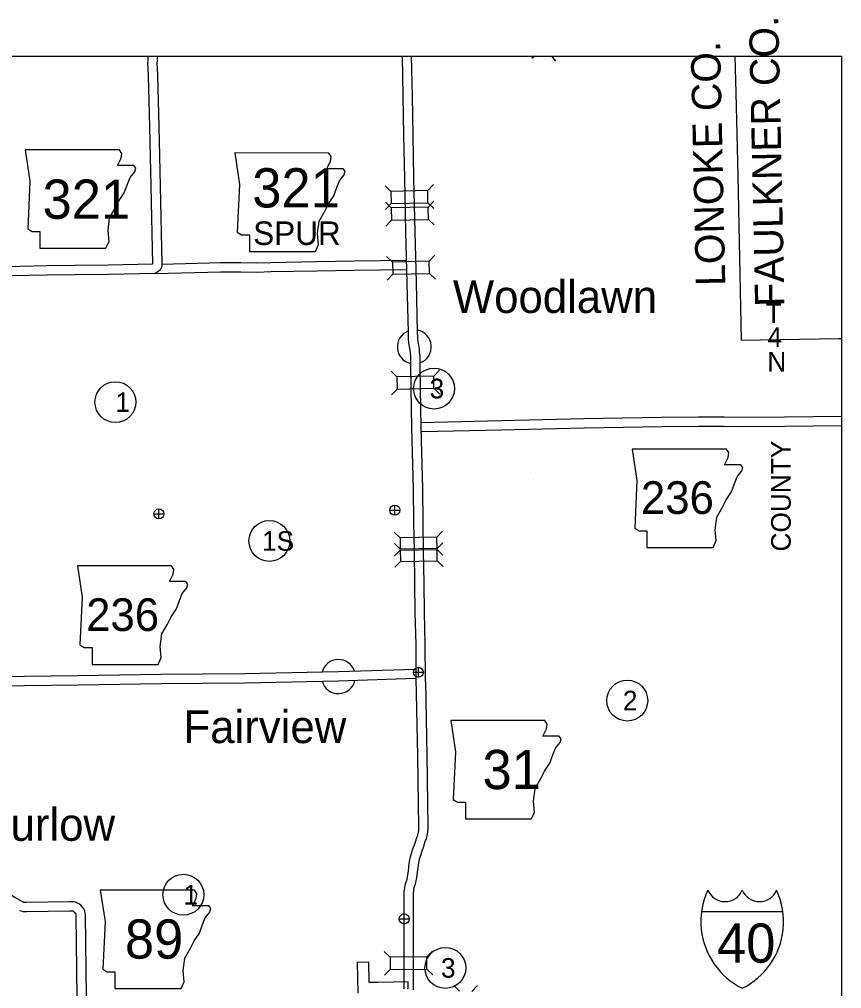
# Model space of a CAD drawing. Extents: x 1127717 to 1741049, y 2026793 to 2244711.
# Drawn here: x 1256180 to 1269452, y 2140586 to 2156238 of the extents above; entities that cross this region are included whole.
import ezdxf

# ---------------------------------------------------------------- set-up
doc = ezdxf.new("R2010")
doc.units = 0
for name, color, linetype in [('1', 7, 'Continuous'), ('10', 7, 'Continuous'), ('2', 7, 'Continuous'), ('20', 7, 'Continuous'), ('21', 7, 'Continuous'), ('23', 7, 'Continuous'), ('24', 7, 'Continuous'), ('26', 7, 'Continuous'), ('27', 7, 'Continuous'), ('30', 7, 'Continuous'), ('6', 7, 'Continuous'), ('Level 30', 7, 'Continuous')]:
    doc.layers.add(name, color=color, linetype=linetype)

msp = doc.modelspace()

# ---------------------------------------------------------------- linework, layer by layer
at = {"layer": '1'}
msp.add_lwpolyline([(1238438, 2155644), (1269452, 2155644), (1269452, 2123596), (1238438, 2123596)], close=True, dxfattribs=at)
at = {"layer": '10'}
for points in [[(1258253, 2155644), (1258252, 2155577), (1258250, 2155524), (1258252, 2155447), (1258257, 2155320), (1258274, 2154716), (1258287, 2154267), (1258300, 2153544), (1258330, 2152283)], [(1258403, 2155644), (1258402, 2155572), (1258400, 2155524), (1258402, 2155452), (1258407, 2155324), (1258424, 2154720), (1258437, 2154271), (1258450, 2153547), (1258480, 2152298), (1258481, 2152259), (1258474, 2152233), (1258463, 2152211), (1258442, 2152181), (1258420, 2152165), (1258401, 2152153), (1258374, 2152134)], [(1262356, 2155644), (1262369, 2154994), (1262382, 2154373), (1262394, 2153669), (1262414, 2152805), (1262433, 2151979), (1262453, 2151186), (1262455, 2151092), (1262463, 2151005), (1262473, 2150957), (1262482, 2150899), (1262486, 2150851), (1262495, 2150786), (1262494, 2150645), (1262500, 2150281), (1262509, 2149646), (1262526, 2149047), (1262537, 2148654), (1262541, 2148124), (1262550, 2147645), (1262559, 2147129), (1262562, 2146660)], [(1262506, 2155644), (1262519, 2154997), (1262532, 2154376), (1262544, 2153672), (1262564, 2152808), (1262583, 2151983), (1262603, 2151190), (1262605, 2151100), (1262612, 2151027), (1262621, 2150983), (1262631, 2150917), (1262635, 2150868), (1262645, 2150795), (1262644, 2150646), (1262650, 2150284), (1262659, 2149649), (1262676, 2149052), (1262687, 2148657), (1262691, 2148126), (1262700, 2147648), (1262709, 2147130), (1262712, 2146661)], [(1258480, 2152287), (1259431, 2152310), (1259754, 2152310), (1260012, 2152307), (1260240, 2152314), (1260976, 2152329), (1261586, 2152340), (1262425, 2152347)], [(1258330, 2152283), (1257618, 2152268), (1257079, 2152262), (1256625, 2152256), (1255747, 2152239), (1255057, 2152225), (1254450, 2152215), (1254187, 2152211), (1253903, 2152201), (1253598, 2152196), (1253075, 2152186)], [(1258374, 2152134), (1259433, 2152160), (1259753, 2152160), (1260013, 2152157), (1260244, 2152164), (1260979, 2152179), (1261588, 2152190), (1262428, 2152197)], [(1258374, 2152134), (1257621, 2152118), (1257081, 2152112), (1256627, 2152106), (1255750, 2152089), (1255059, 2152075), (1254452, 2152065), (1254191, 2152061), (1253907, 2152051), (1253600, 2152046), (1253078, 2152036)], [(1269452, 2149824), (1268531, 2149813), (1267859, 2149808), (1267554, 2149814), (1267143, 2149814), (1266551, 2149808), (1265291, 2149789), (1263954, 2149756), (1262665, 2149724)], [(1269452, 2149674), (1268533, 2149663), (1267859, 2149658), (1267553, 2149664), (1267144, 2149664), (1266553, 2149658), (1265294, 2149639), (1263957, 2149606), (1262674, 2149575)], [(1262562, 2146658), (1262577, 2146138), (1262581, 2145599), (1262608, 2144346)], [(1262712, 2146662), (1262727, 2146141), (1262731, 2145601), (1262732, 2145541)], [(1254588, 2145470), (1255822, 2145476), (1257131, 2145492), (1258467, 2145513), (1259821, 2145523), (1261333, 2145555), (1262576, 2145597)], [(1254592, 2145620), (1255821, 2145626), (1257129, 2145642), (1258465, 2145663), (1259819, 2145673), (1261329, 2145705), (1262572, 2145747)], [(1262734, 2145541), (1262758, 2144349), (1262771, 2143191), (1262770, 2143112), (1262758, 2143058), (1262745, 2143005), (1262726, 2142955), (1262702, 2142881), (1262668, 2142787), (1262652, 2142737), (1262632, 2142671), (1262622, 2142619), (1262610, 2142534), (1262601, 2142466), (1262594, 2142407), (1262584, 2142354), (1262574, 2142300), (1262562, 2142257), (1262549, 2142214), (1262543, 2142184), (1262539, 2142160), (1262535, 2142133), (1262534, 2142099), (1262534, 2142047), (1262537, 2141968), (1262535, 2141165), (1262538, 2140818), (1262536, 2140644), (1262535, 2140605), (1262535, 2140566)], [(1262608, 2144347), (1262621, 2143191), (1262620, 2143130), (1262612, 2143093), (1262601, 2143049), (1262585, 2143004), (1262561, 2142930), (1262526, 2142837), (1262508, 2142782), (1262486, 2142706), (1262474, 2142643), (1262461, 2142554), (1262453, 2142485), (1262446, 2142430), (1262437, 2142382), (1262428, 2142334), (1262418, 2142300), (1262403, 2142252), (1262395, 2142211), (1262390, 2142182), (1262385, 2142145), (1262384, 2142101), (1262385, 2142044), (1262387, 2141965), (1262385, 2141164), (1262388, 2140818), (1262386, 2140648), (1262385, 2140608), (1262385, 2140589), (1262381, 2140578)], [(1256242, 2141982), (1256202, 2142001), (1256109, 2142059), (1255955, 2142152), (1255752, 2142269), (1255520, 2142382), (1255074, 2142597), (1255029, 2142612), (1254988, 2142619), (1254945, 2142631), (1254924, 2142635)], [(1257115, 2140445), (1257096, 2141771), (1257095, 2141787), (1257092, 2141792), (1257083, 2141805), (1257068, 2141822), (1257061, 2141827), (1257047, 2141834), (1257042, 2141836), (1257039, 2141837), (1257024, 2141837), (1256991, 2141836), (1256298, 2141825), (1256270, 2141826), (1256246, 2141827), (1256210, 2141835), (1256184, 2141844)], [(1257265, 2140447), (1257246, 2141776), (1257244, 2141804), (1257238, 2141840), (1257218, 2141873), (1257201, 2141899), (1257171, 2141932), (1257141, 2141955), (1257107, 2141972), (1257086, 2141980), (1257055, 2141987), (1257022, 2141987), (1256986, 2141986), (1256300, 2141975), (1256277, 2141975), (1256266, 2141976), (1256251, 2141979), (1256234, 2141985)]]:
    msp.add_lwpolyline(points, dxfattribs=at)
at = {"layer": '2'}
msp.add_lwpolyline([(1267729, 2155644), (1267745, 2155053), (1267774, 2153717), (1267804, 2152380), (1267830, 2151060), (1269404, 2151085), (1269452, 2151087)], dxfattribs=at)
at = {"layer": '20'}
for p, q in [((1264504, 2155644), (1264454, 2155604)), ((1264770, 2155644), (1264836, 2155562)), ((1262177, 2153461), (1262082, 2153552)), ((1262771, 2153474), (1262862, 2153570)), ((1262183, 2153194), (1262088, 2153285)), ((1262181, 2153263), (1262090, 2153168)), ((1262775, 2153276), (1262871, 2153185)), ((1262777, 2153207), (1262868, 2153303)), ((1262188, 2152996), (1262096, 2152900)), ((1262781, 2153009), (1262877, 2152918)), ((1262203, 2152320), (1262108, 2152411)), ((1262797, 2152334), (1262888, 2152429)), ((1262208, 2152122), (1262117, 2152026)), ((1262802, 2152136), (1262897, 2152045)), ((1262275, 2150467), (1262180, 2150558)), ((1262869, 2150478), (1262960, 2150573)), ((1262278, 2150269), (1262187, 2150174)), ((1262872, 2150280), (1262967, 2150188)), ((1262324, 2147867), (1262229, 2147958)), ((1262918, 2147877), (1263010, 2147972)), ((1262922, 2147692), (1263013, 2147787)), ((1262328, 2147683), (1262233, 2147774)), ((1262328, 2147669), (1262236, 2147574)), ((1262922, 2147679), (1263017, 2147588)), ((1262331, 2147485), (1262239, 2147390)), ((1262925, 2147494), (1263020, 2147402)), ((1262164, 2141094), (1262070, 2141187)), ((1262758, 2141098), (1262850, 2141192)), ((1262165, 2140896), (1262072, 2140802)), ((1262759, 2140900), (1262853, 2140808)), ((1263285, 2140542), (1263192, 2140635)), ((1263483, 2140541), (1263577, 2140634))]:
    msp.add_line(p, q, dxfattribs=at)
for points in [[(1262181, 2153263), (1262775, 2153276), (1262771, 2153474), (1262177, 2153461)], [(1262777, 2153207), (1262183, 2153194), (1262188, 2152996), (1262781, 2153009)], [(1262797, 2152334), (1262203, 2152320), (1262208, 2152122), (1262802, 2152136)], [(1262278, 2150269), (1262872, 2150280), (1262869, 2150478), (1262275, 2150467)], [(1262328, 2147669), (1262922, 2147679), (1262918, 2147877), (1262324, 2147867)], [(1262331, 2147485), (1262925, 2147494), (1262922, 2147692), (1262328, 2147683)], [(1262758, 2141098), (1262164, 2141094), (1262165, 2140896), (1262759, 2140900)]]:
    msp.add_lwpolyline(points, close=True, dxfattribs=at)
at = {"layer": '21'}
for points in [[(1256275, 2154133), (1256351, 2153626), (1256318, 2152856), (1256385, 2152813), (1256512, 2152813), (1256512, 2152543), (1257578, 2152543), (1257629, 2152653), (1257612, 2152830), (1257637, 2153033), (1257730, 2153194), (1257789, 2153313), (1257874, 2153439), (1257925, 2153575), (1257967, 2153685), (1258043, 2153778), (1258060, 2153837), (1258026, 2153879), (1257764, 2153879), (1257823, 2153998), (1257832, 2154074), (1257797, 2154132)], [(1259655, 2154081), (1259731, 2153573), (1259697, 2152804), (1259765, 2152761), (1259892, 2152761), (1259892, 2152491), (1260958, 2152491), (1261008, 2152601), (1260991, 2152778), (1261017, 2152981), (1261110, 2153142), (1261169, 2153260), (1261254, 2153387), (1261304, 2153523), (1261347, 2153633), (1261423, 2153726), (1261440, 2153785), (1261406, 2153827), (1261144, 2153827), (1261203, 2153946), (1261211, 2154022), (1261176, 2154080)], [(1266073, 2149300), (1266149, 2148793), (1266115, 2148023), (1266183, 2147981), (1266310, 2147981), (1266310, 2147710), (1267376, 2147710), (1267426, 2147820), (1267410, 2147997), (1267435, 2148200), (1267528, 2148361), (1267587, 2148480), (1267672, 2148607), (1267723, 2148742), (1267765, 2148852), (1267841, 2148945), (1267858, 2149004), (1267824, 2149046), (1267562, 2149046), (1267621, 2149165), (1267629, 2149241), (1267594, 2149299)], [(1257116, 2147412), (1257192, 2146905), (1257158, 2146135), (1257226, 2146093), (1257353, 2146093), (1257353, 2145822), (1258419, 2145822), (1258470, 2145932), (1258453, 2146110), (1258478, 2146313), (1258571, 2146473), (1258630, 2146592), (1258715, 2146719), (1258766, 2146854), (1258808, 2146964), (1258884, 2147057), (1258901, 2147116), (1258867, 2147158), (1258605, 2147158), (1258664, 2147277), (1258673, 2147353), (1258638, 2147411)], [(1263142, 2144917), (1263218, 2144410), (1263184, 2143640), (1263252, 2143598), (1263379, 2143598), (1263379, 2143327), (1264444, 2143327), (1264495, 2143437), (1264478, 2143615), (1264504, 2143818), (1264597, 2143979), (1264656, 2144097), (1264741, 2144224), (1264791, 2144359), (1264834, 2144469), (1264910, 2144562), (1264927, 2144621), (1264893, 2144664), (1264631, 2144664), (1264690, 2144782), (1264698, 2144858), (1264663, 2144917)], [(1257486, 2142177), (1257562, 2141670), (1257529, 2140900), (1257596, 2140858), (1257723, 2140858), (1257723, 2140587), (1258789, 2140587), (1258840, 2140697), (1258823, 2140875), (1258848, 2141078), (1258941, 2141238), (1259000, 2141357), (1259085, 2141484), (1259136, 2141619), (1259178, 2141729), (1259254, 2141822), (1259271, 2141881), (1259237, 2141924), (1258975, 2141924), (1259034, 2142042), (1259043, 2142118), (1259008, 2142177)]]:
    msp.add_lwpolyline(points, close=True, dxfattribs=at)
at = {"layer": '23'}
msp.add_line((1267193, 2141833), (1268503, 2141833), dxfattribs=at)
for centre, radius, start, end in [((1268411, 2141662), 1230, 155.2204, 185.7928), ((1267571, 2142291), 300, 202.1459, 337.3414), ((1268125, 2142291), 300, 202.6586, 337.8541), ((1267285, 2141662), 1230, 354.2072, 24.7796), ((1268388, 2141673), 1209, 186.3923, 243.4571), ((1267308, 2141673), 1209, 296.5429, 353.6077)]:
    msp.add_arc(centre, radius, start, end, dxfattribs=at)
at = {"layer": '24'}
for centre, start, end in [((1265546, 2155918), 264.8657, 275.1343), ((1262555, 2150950), 112.4902, 256.9056), ((1262555, 2150950), 290.09, 79.785), ((1261329, 2145625), 19.7855, 163.6903), ((1261329, 2145625), 195.9697, 346.6075)]:
    msp.add_arc(centre, 275, start, end, dxfattribs=at)
at = {"layer": '26'}
for p, q in [((1258351, 2148252), (1258514, 2148252)), ((1258432, 2148171), (1258432, 2148333)), ((1262157, 2148313), (1262320, 2148313)), ((1262239, 2148231), (1262239, 2148394)), ((1262620, 2145612), (1262620, 2145775)), ((1262539, 2145694), (1262701, 2145694)), ((1262311, 2141711), (1262473, 2141711)), ((1262392, 2141629), (1262392, 2141792))]:
    msp.add_line(p, q, dxfattribs=at)
for centre in [(1258432, 2148252), (1262239, 2148313), (1262620, 2145694), (1262392, 2141711)]:
    msp.add_circle(centre, 81.2, dxfattribs=at)
at = {"layer": '27'}
for centre in [(1262873, 2150276), (1257730, 2150057), (1260215, 2147815), (1265992, 2145237), (1258827, 2142102), (1263056, 2140920)]:
    msp.add_circle(centre, 330, dxfattribs=at)
at = {"layer": '30'}
msp.add_line((1264429, 2148925), (1264429, 2148925), dxfattribs=at)
at = {"layer": '6'}
msp.add_lwpolyline([(1262452, 2140584), (1262454, 2140601), (1262455, 2140615), (1262456, 2140644), (1262457, 2140669), (1262458, 2140698), (1261970, 2140686), (1261824, 2140683), (1261818, 2141014), (1261631, 2141010), (1261642, 2140513)], dxfattribs=at)

# ---------------------------------------------------------------- texts
at = {"layer": '21'}
for s, height, p in [('321', 633.6, (1259939, 2153201)), ('321', 633.6, (1256554, 2153018)), ('SPUR', 380.2, (1259954, 2152595)), ('236', 528, (1266212, 2148251)), ('236', 528, (1257257, 2146361)), ('31', 633.6, (1263655, 2143808)), ('89', 633.6, (1257883, 2141070))]:
    msp.add_text(s, height=height, dxfattribs=at).set_placement(p)
at = {"layer": '23'}
msp.add_text('40', height=633.6, dxfattribs=at).set_placement((1267440, 2141004))
at = {"layer": '24'}
for s, p in [('Woodlawn', (1263177, 2151497)), ('Fairview', (1258829, 2144551)), ('Furlow', (1255606, 2142973))]:
    msp.add_text(s, height=528, dxfattribs=at).set_placement(p)
at = {"layer": '27'}
for s, height, p in [('3', 317, (1262802, 2150118)), ('1', 317, (1257730, 2149899)), ('1S', 316.8, (1260097, 2147657)), ('2', 317, (1265921, 2145079)), ('1', 317, (1258827, 2141943)), ('3', 317, (1262985, 2140762))]:
    msp.add_text(s, height=height, dxfattribs=at).set_placement(p)
at = {"layer": '30'}
for s, p in [('T', (1268225, 2151334)), ('4', (1268254, 2150950)), ('N', (1268251, 2150551))]:
    msp.add_text(s, height=317, dxfattribs=at).set_placement(p)
msp.add_text('COUNTY', height=316.8, rotation=90, dxfattribs=at).set_placement((1268631, 2147645))
at = {"layer": 'Level 30'}
for s, p in [('FAULKNER CO.', (1268531, 2151601)), ('LONOKE CO.', (1267575, 2151937))]:
    msp.add_text(s, height=475.2, rotation=91.2354, dxfattribs=at).set_placement(p)

doc.saveas('drawing.dxf')
